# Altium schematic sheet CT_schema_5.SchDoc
size 573 x 363 mm
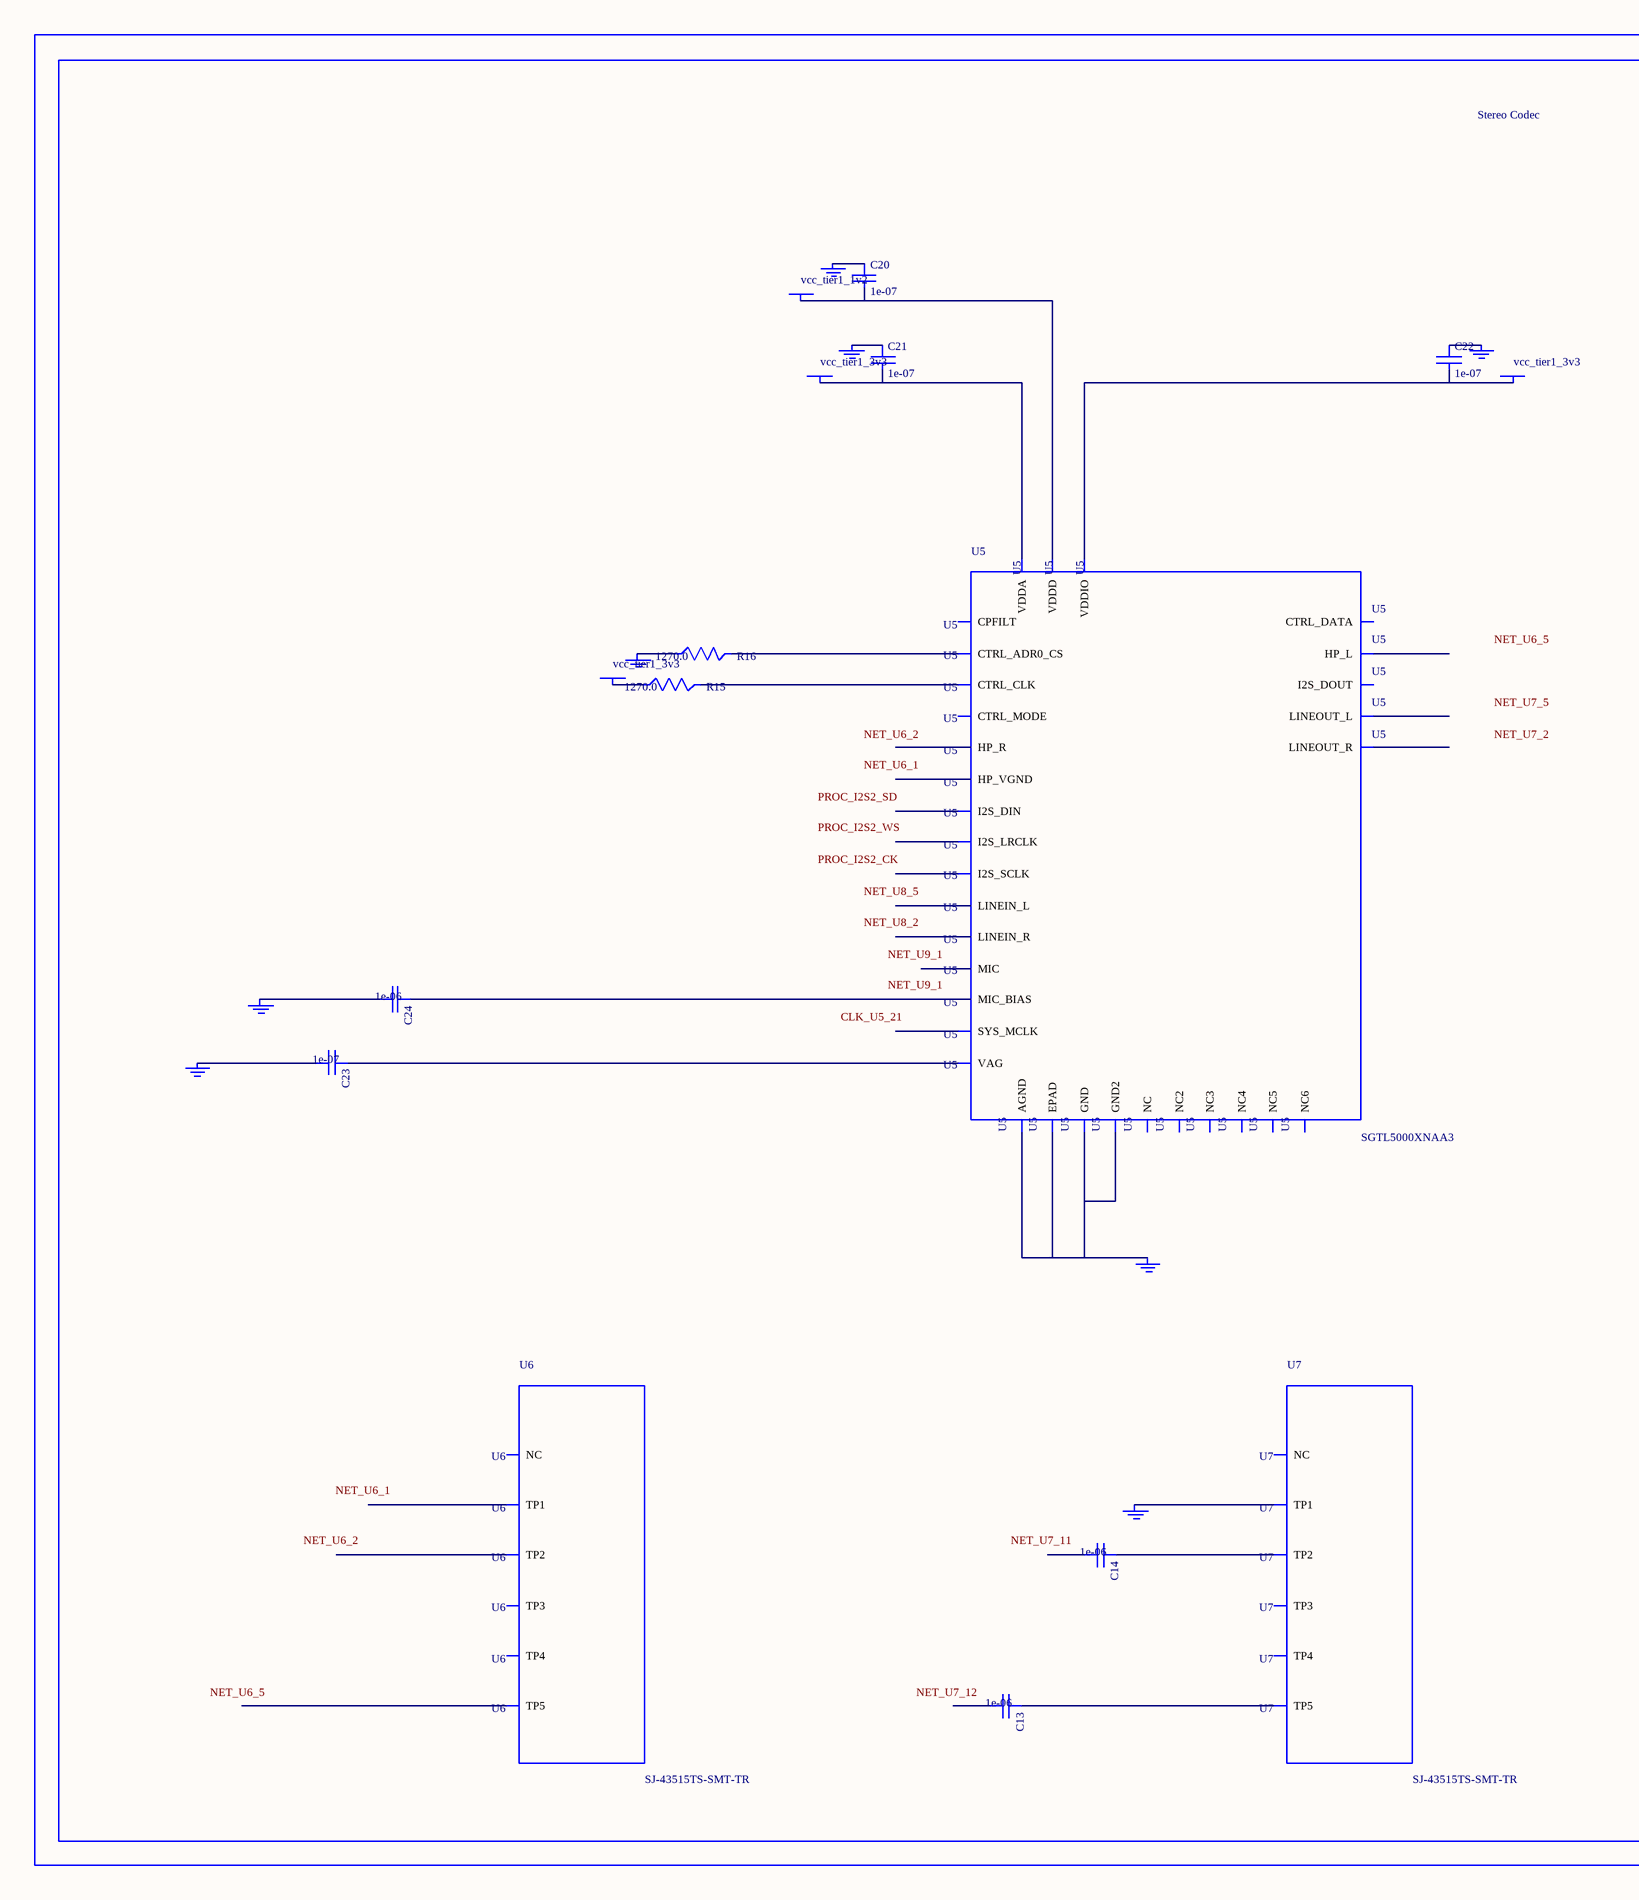
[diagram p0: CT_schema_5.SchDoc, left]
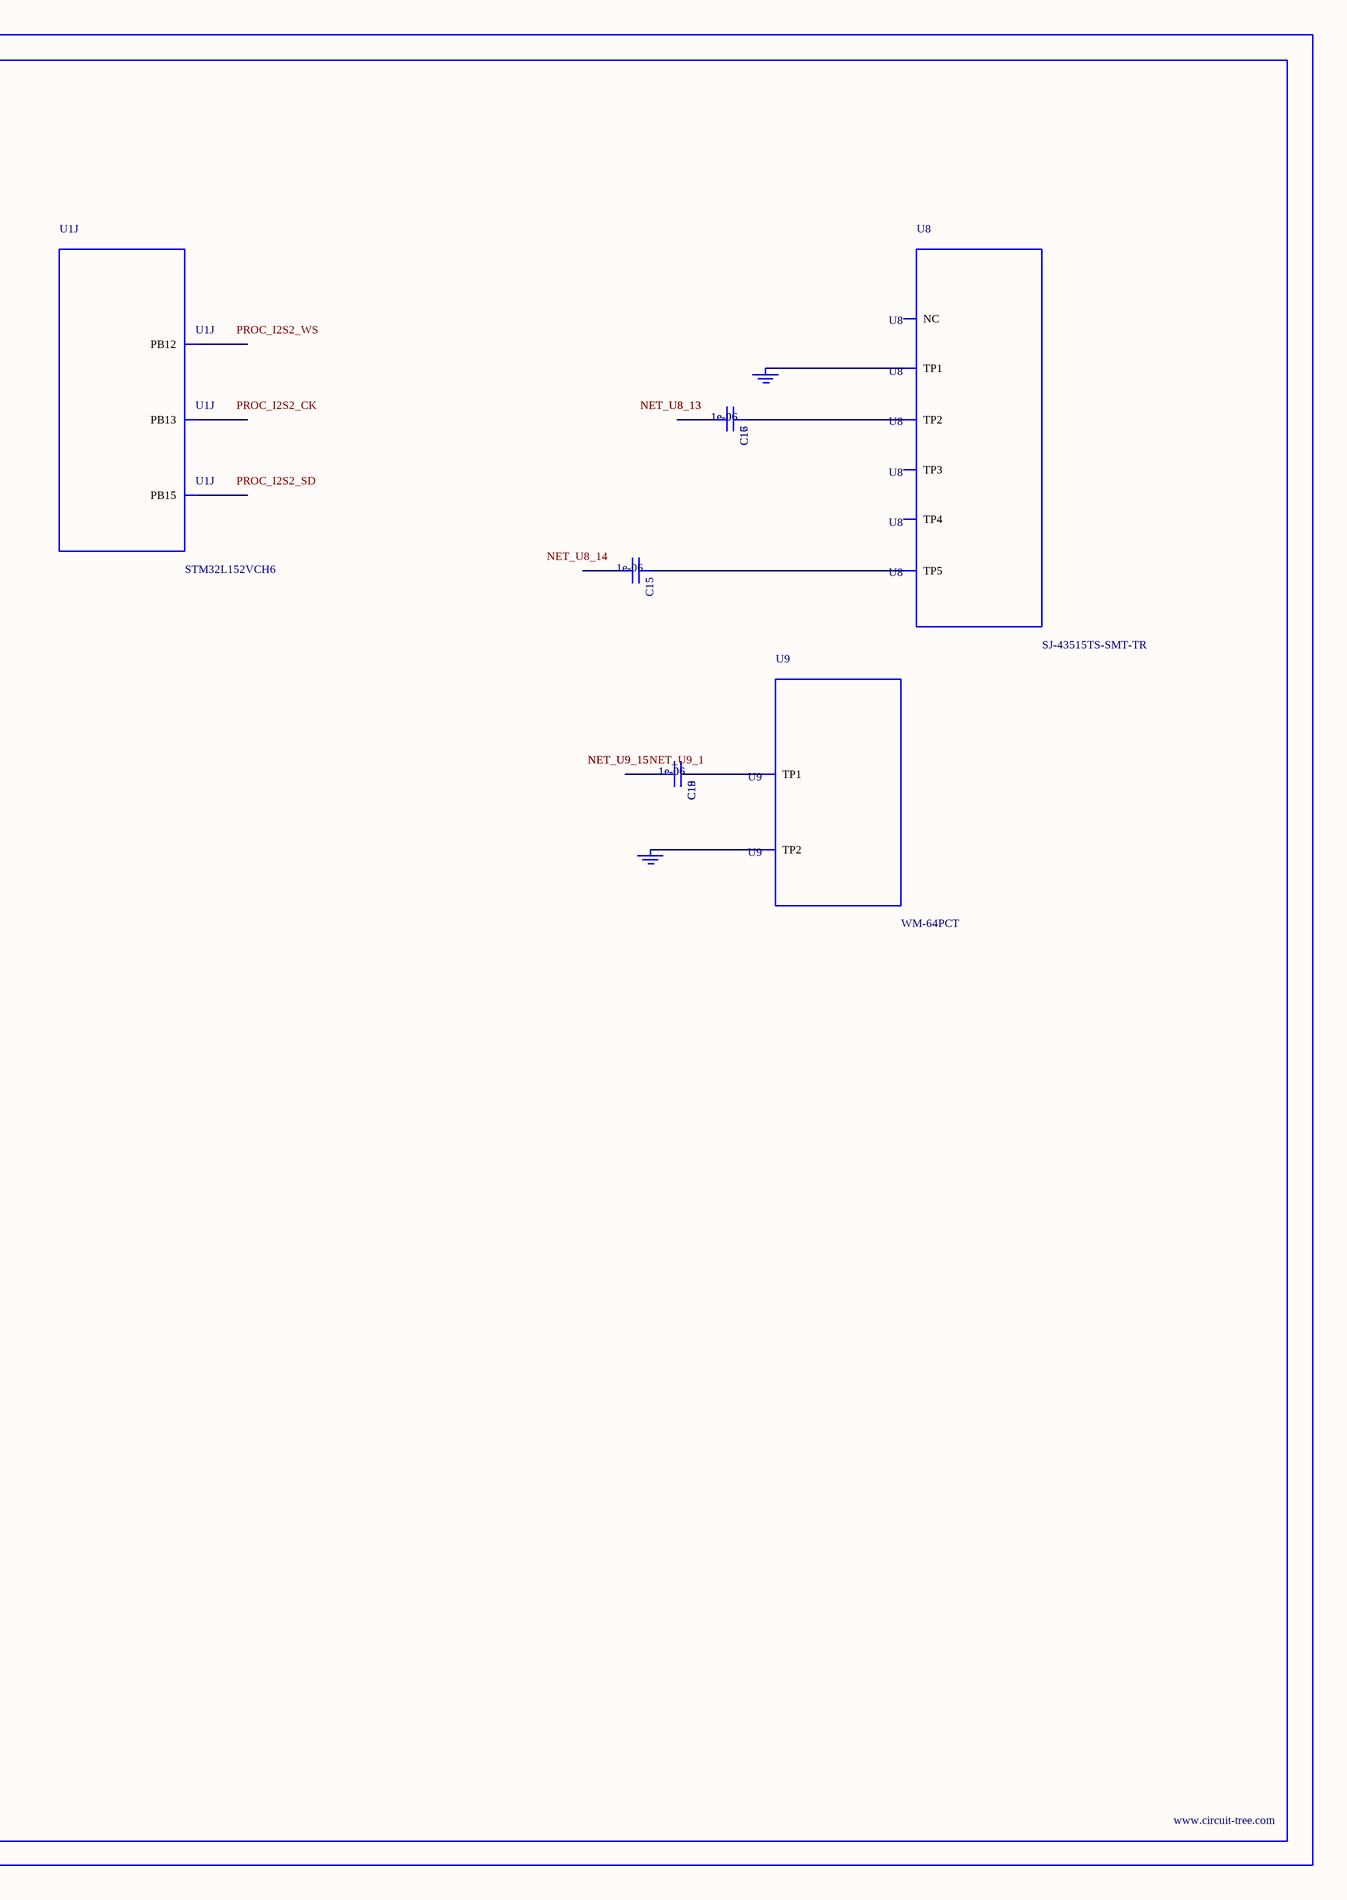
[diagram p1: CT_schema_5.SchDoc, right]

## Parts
BORDER4  (no value)
C13  1e-06  [C0603]
C14  1e-06  [C0603]
C15  1e-06  [C0603]
C16  1e-06  [C0603]
C17  1e-06  [C0603]
C18  1e-06  [C0603]
C19  1e-06  [C0603]
C20  1e-07  [C0402]
C21  1e-07  [C0402]
C22  1e-07  [C0402]
C23  1e-07  [C0402]
C24  1e-06  [C0603]
GND_INSTANCE_4_0  (no value)
GND_INSTANCE_4_1  (no value)
GND_INSTANCE_4_2  (no value)
GND_INSTANCE_4_3  (no value)
GND_INSTANCE_4_4  (no value)
GND_INSTANCE_4_5  (no value)
GND_INSTANCE_4_6  (no value)
GND_INSTANCE_4_7  (no value)
GND_INSTANCE_4_8  (no value)
GND_INSTANCE_4_9  (no value)
GND_INSTANCE_4_10  (no value)
POWER_INSTANCE_4_0  vcc_tier1_3v3
POWER_INSTANCE_4_1  vcc_tier1_3v3
POWER_INSTANCE_4_2  vcc_tier1_3v3
POWER_INSTANCE_4_3  vcc_tier1_1v2
R15  1270.0  [R0603]
R16  1270.0  [R0603]
U1  STM32L152VCH6  [UFBGA100]  (part J of 11)
U5  SGTL5000XNAA3  [QFN-32]
U6  SJ-43515TS-SMT-TR  [SJ-43515TS-SMT-TR]
U7  SJ-43515TS-SMT-TR  [SJ-43515TS-SMT-TR]
U8  SJ-43515TS-SMT-TR  [SJ-43515TS-SMT-TR]
U9  WM-64PCT  [WM-64PC]

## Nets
NetC13_1: C13.1 U7.5(TP5)
NetC14_1: C14.1 U7.2(TP2)
NetC15_1: C15.1 U8.5(TP5)
NetC16_1: C16.1 C17.1 U8.2(TP2)
NetC16_2: C16.2 C17.2
NetC18_1: C18.1 C19.1 U9.1(TP1)
NetC18_2: C18.2 C19.2
NetC20_1: C20.1 GND_INSTANCE_4_5.0(GND)
NetC20_2: C20.2 POWER_INSTANCE_4_3.0(PWR) U5.30(VDDD)
NetC21_1: C21.1 GND_INSTANCE_4_1.0(GND)
NetC21_2: C21.2 POWER_INSTANCE_4_0.0(PWR) U5.5(VDDA)
NetC22_1: C22.1 GND_INSTANCE_4_4.0(GND)
NetC22_2: C22.2 POWER_INSTANCE_4_1.0(PWR) U5.20(VDDIO)
NetC23_1: C23.1 U5.10(VAG)
NetC23_2: C23.2 GND_INSTANCE_4_2.0(GND)
NetC24_1: C24.1 U5.16(MIC_BIAS)
NetC24_2: C24.2 GND_INSTANCE_4_3.0(GND)
NetGND_INSTANCE_4_0_0: GND_INSTANCE_4_0.0(GND) U5.1(GND) U5.3(GND2) U5.7(AGND) U5.EXP(EPAD)
NetGND_INSTANCE_4_6_0: GND_INSTANCE_4_6.0(GND) R16.1
NetGND_INSTANCE_4_7_0: GND_INSTANCE_4_7.0(GND) U7.1(TP1)
NetGND_INSTANCE_4_8_0: GND_INSTANCE_4_8.0(GND) GND_INSTANCE_4_9.0(GND) U8.1(TP1)
NetGND_INSTANCE_4_10_0: GND_INSTANCE_4_10.0(GND) U9.2(TP2)
NetPOWER_INSTANCE_4_2_0: POWER_INSTANCE_4_2.0(PWR) R15.1
NetR15_2: R15.2 U5.29(CTRL_CLK)
NetR16_2: R16.2 U5.31(CTRL_ADR0_CS)

Not connected (* = marked no-connect by the designer): C13 2; C14 2; C15 2; U1 K10(PB15) K12(PB13) L12(PB12); U5 2(HP_R) 4(HP_VGND) 6(HP_L) 8(NC) 9(NC2) 11(LINEOUT_R) 12(LINEOUT_L) 13(LINEIN_R) 14(LINEIN_L) 15(MIC) 17(NC3) 18(CPFILT) 19(NC4) 21(SYS_MCLK) 22(NC5) 23(I2S_LRCLK) 24(I2S_SCLK) 25(I2S_DOUT) 26(I2S_DIN) 27(CTRL_DATA) 28(NC6) 32(CTRL_MODE); U6 1(TP1) 2(TP2) 3(TP3) 4(TP4) 5(TP5) 6(NC); U7 3(TP3) 4(TP4) 6(NC); U8 3(TP3) 4(TP4) 6(NC)

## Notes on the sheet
- Labels drawn without touching a wire or pin: CLK_U5_21, NET_U6_1, NET_U6_2, NET_U6_5, NET_U7_2, NET_U7_5, NET_U7_11, NET_U7_12, NET_U8_2, NET_U8_5, NET_U8_14, NET_U9_1, PROC_I2S2_CK, PROC_I2S2_SD, PROC_I2S2_WS

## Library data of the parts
BORDER4 = BORDER_PAGE4
C13-C19 C24 = C0603C105K3RACTU
C20-C23 = C0402C104K3RACTU
GND_INSTANCE_4_0-GND_INSTANCE_4_10 = GND
POWER_INSTANCE_4_0-POWER_INSTANCE_4_3 = PWR
R15 R16 = RC0603FR-071K27L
